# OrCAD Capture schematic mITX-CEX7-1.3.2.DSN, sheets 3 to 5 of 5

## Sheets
3 Connectors (2): size D; title: Micro BMC, NVME, USB serial, USB connectors
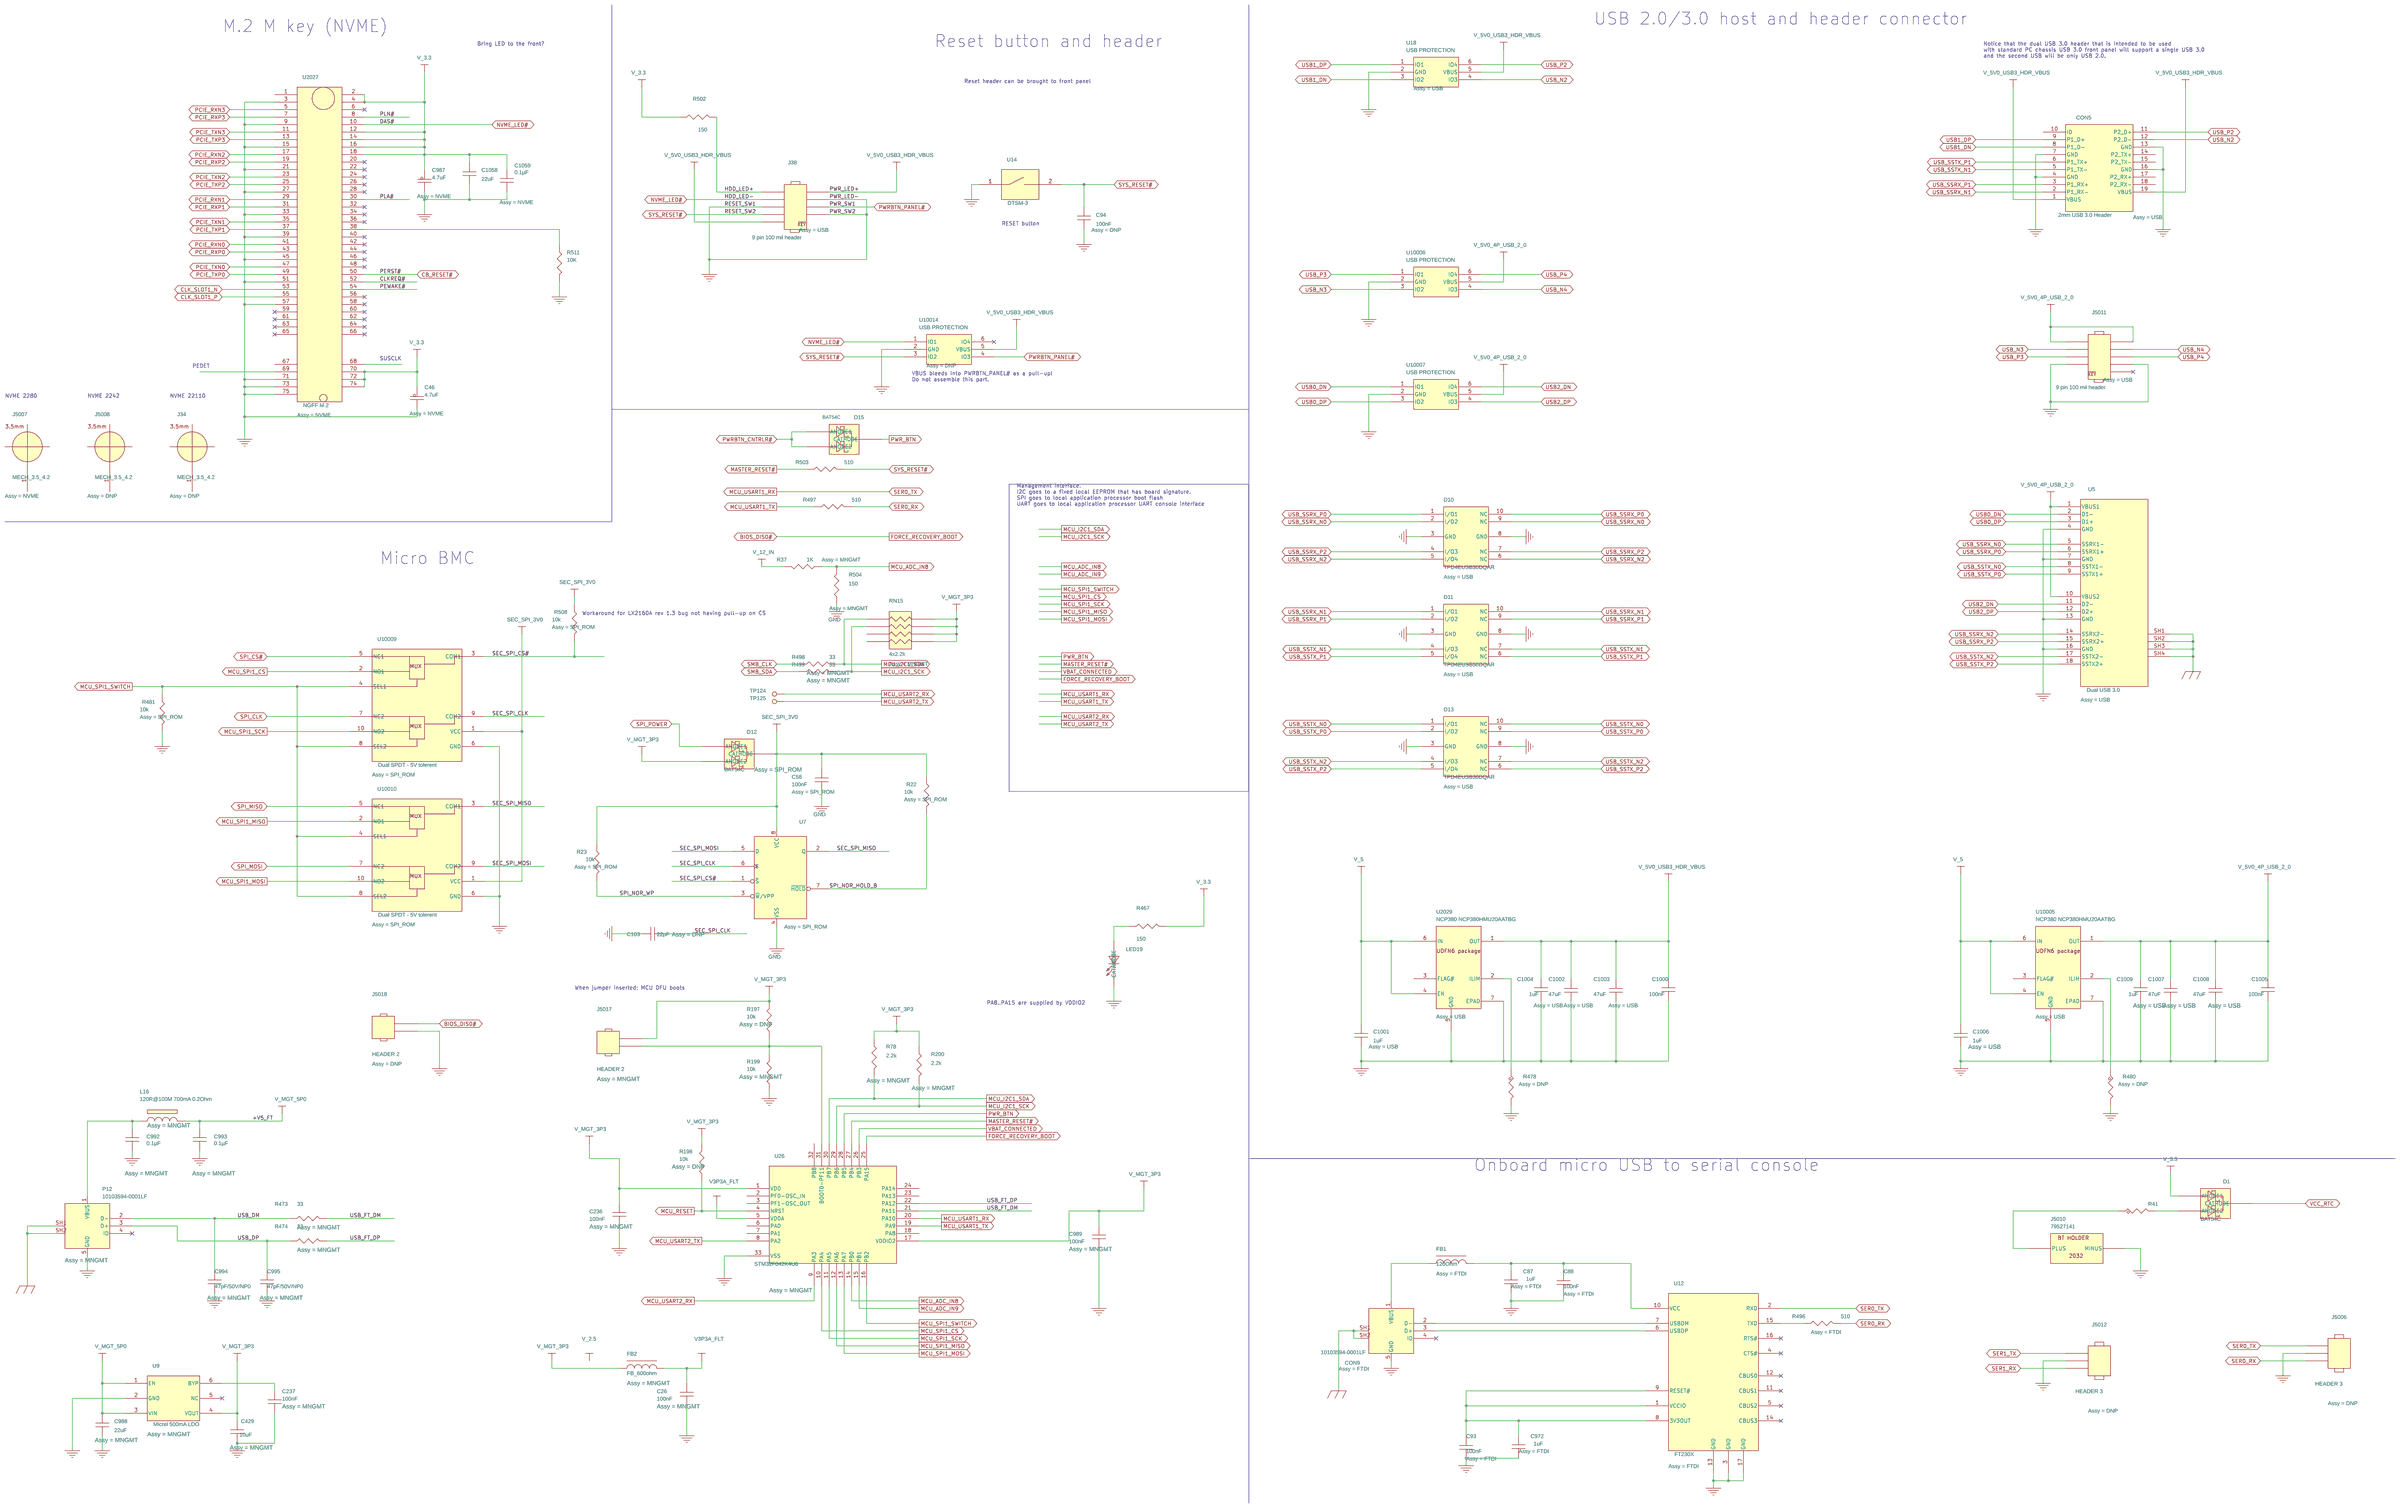
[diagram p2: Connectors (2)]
4 DC-DC: size D; title: ATX, 2x2 SFP+ connectors, power button controller
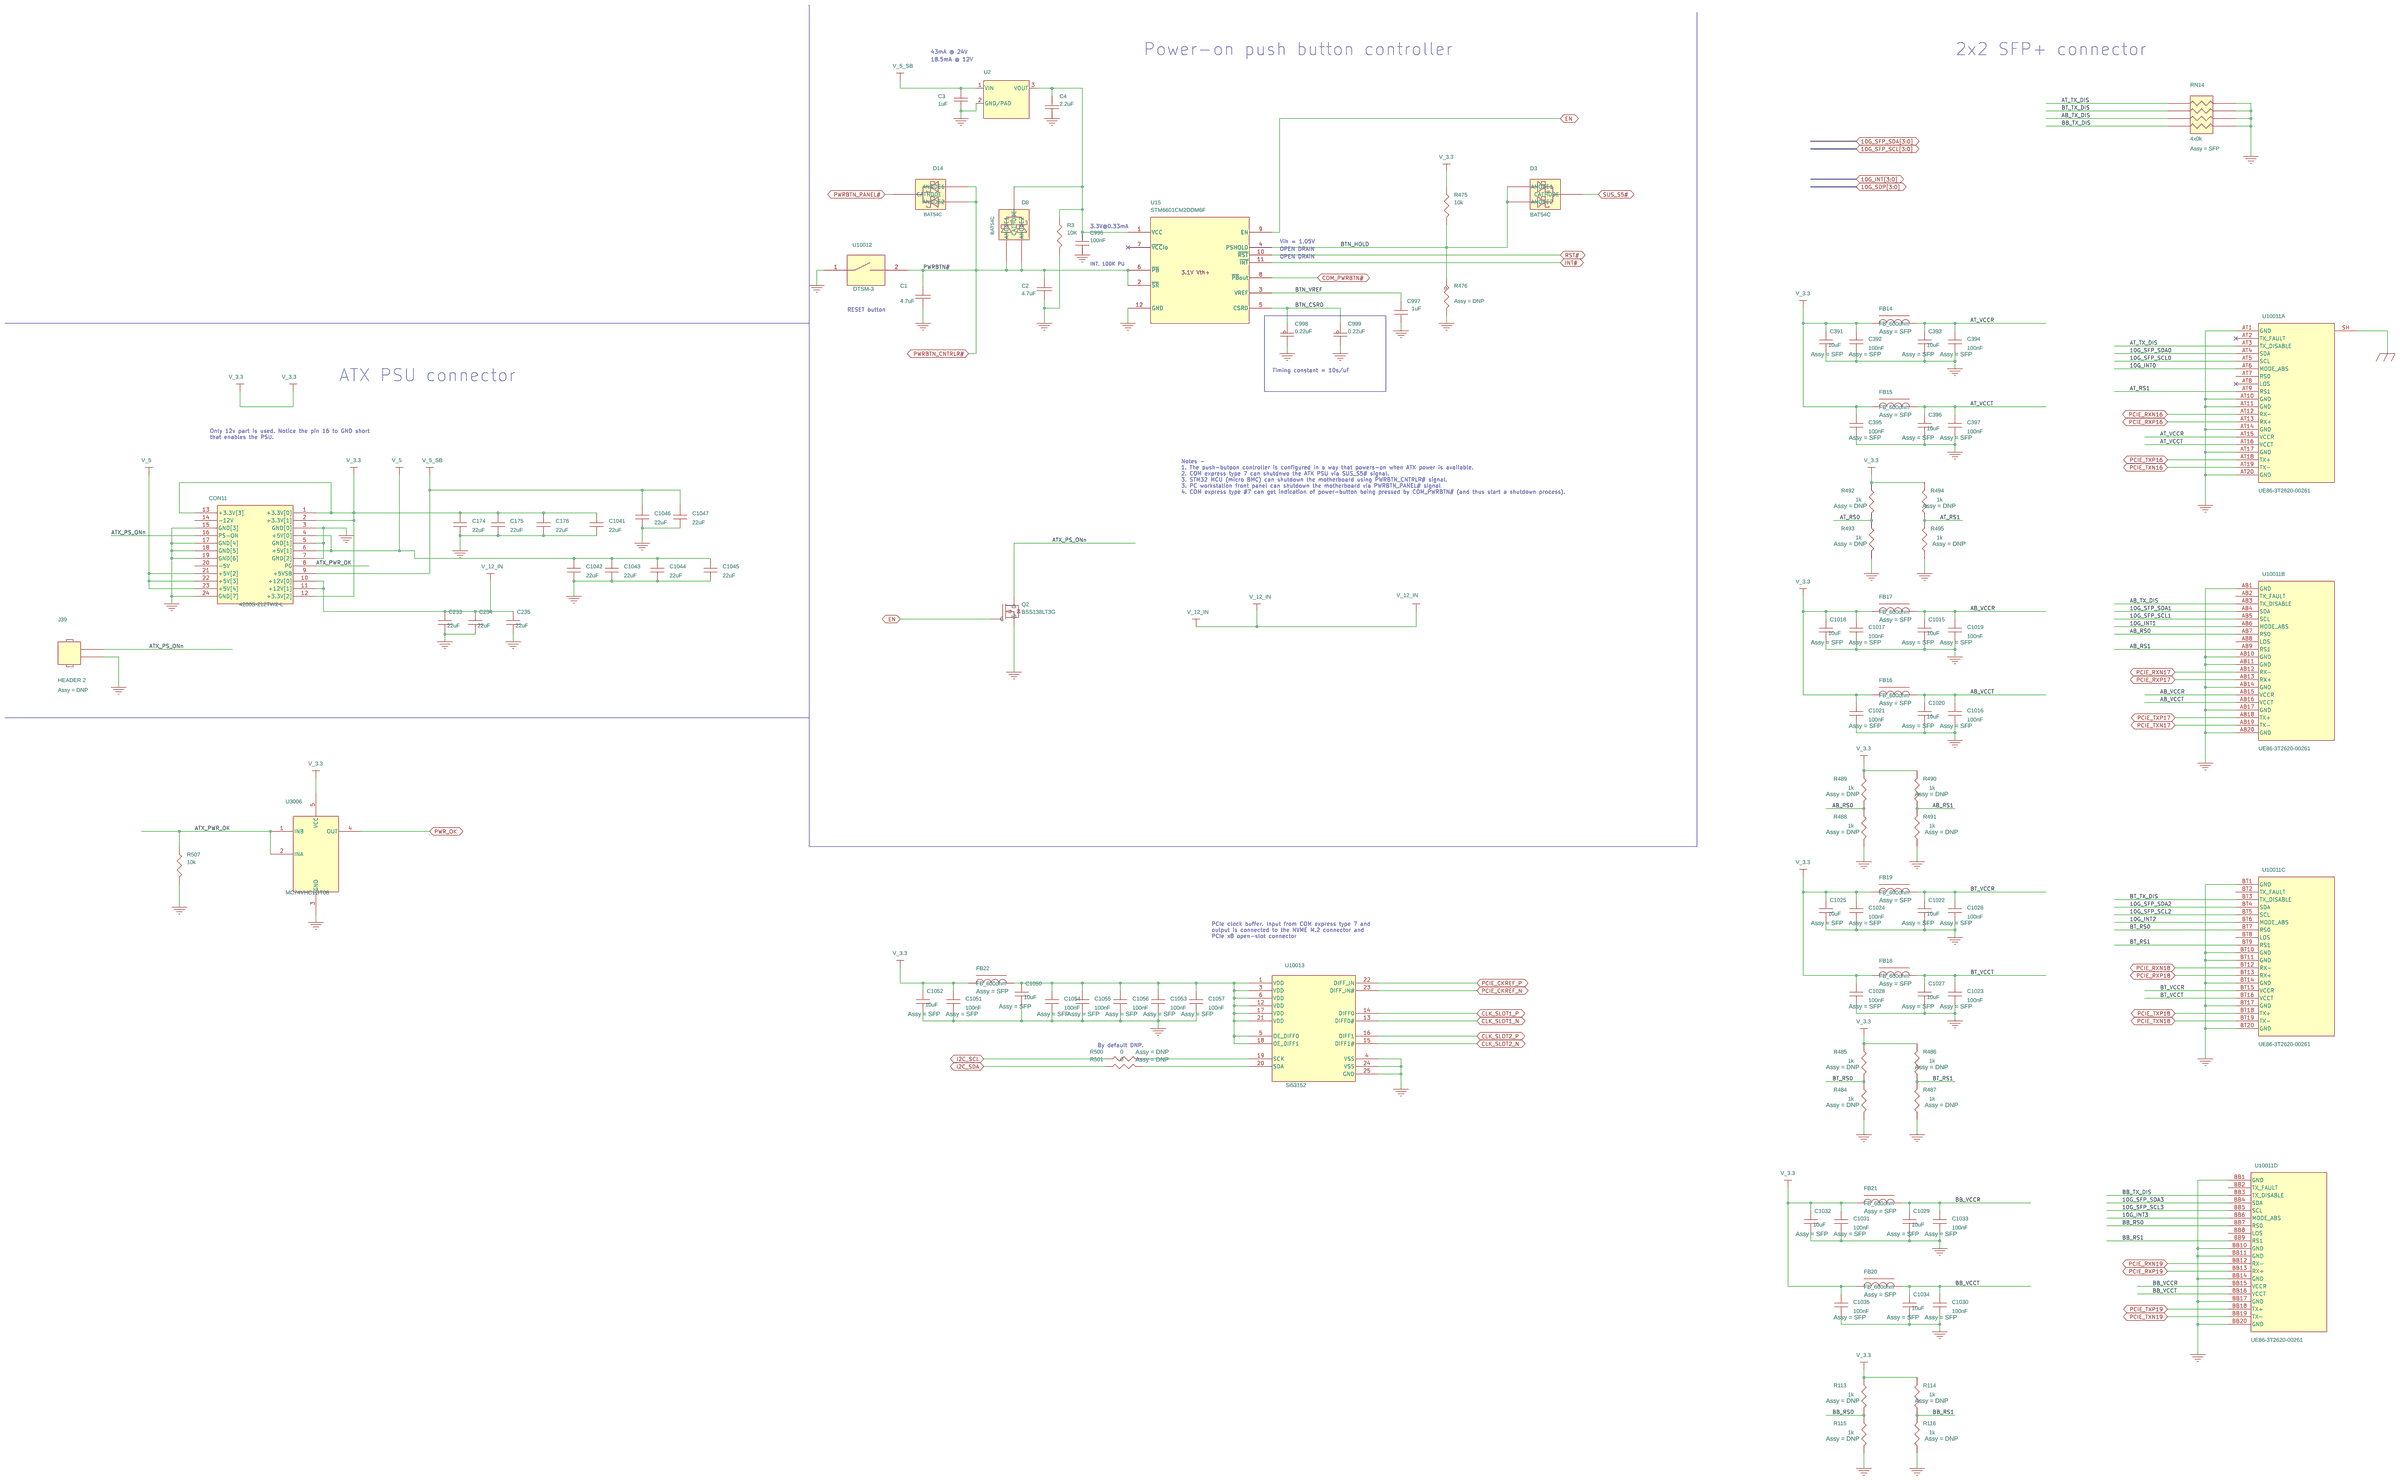
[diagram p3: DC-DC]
5 1588 PTP: size D; title: 1588 PTP - This circuit is not assembled by default
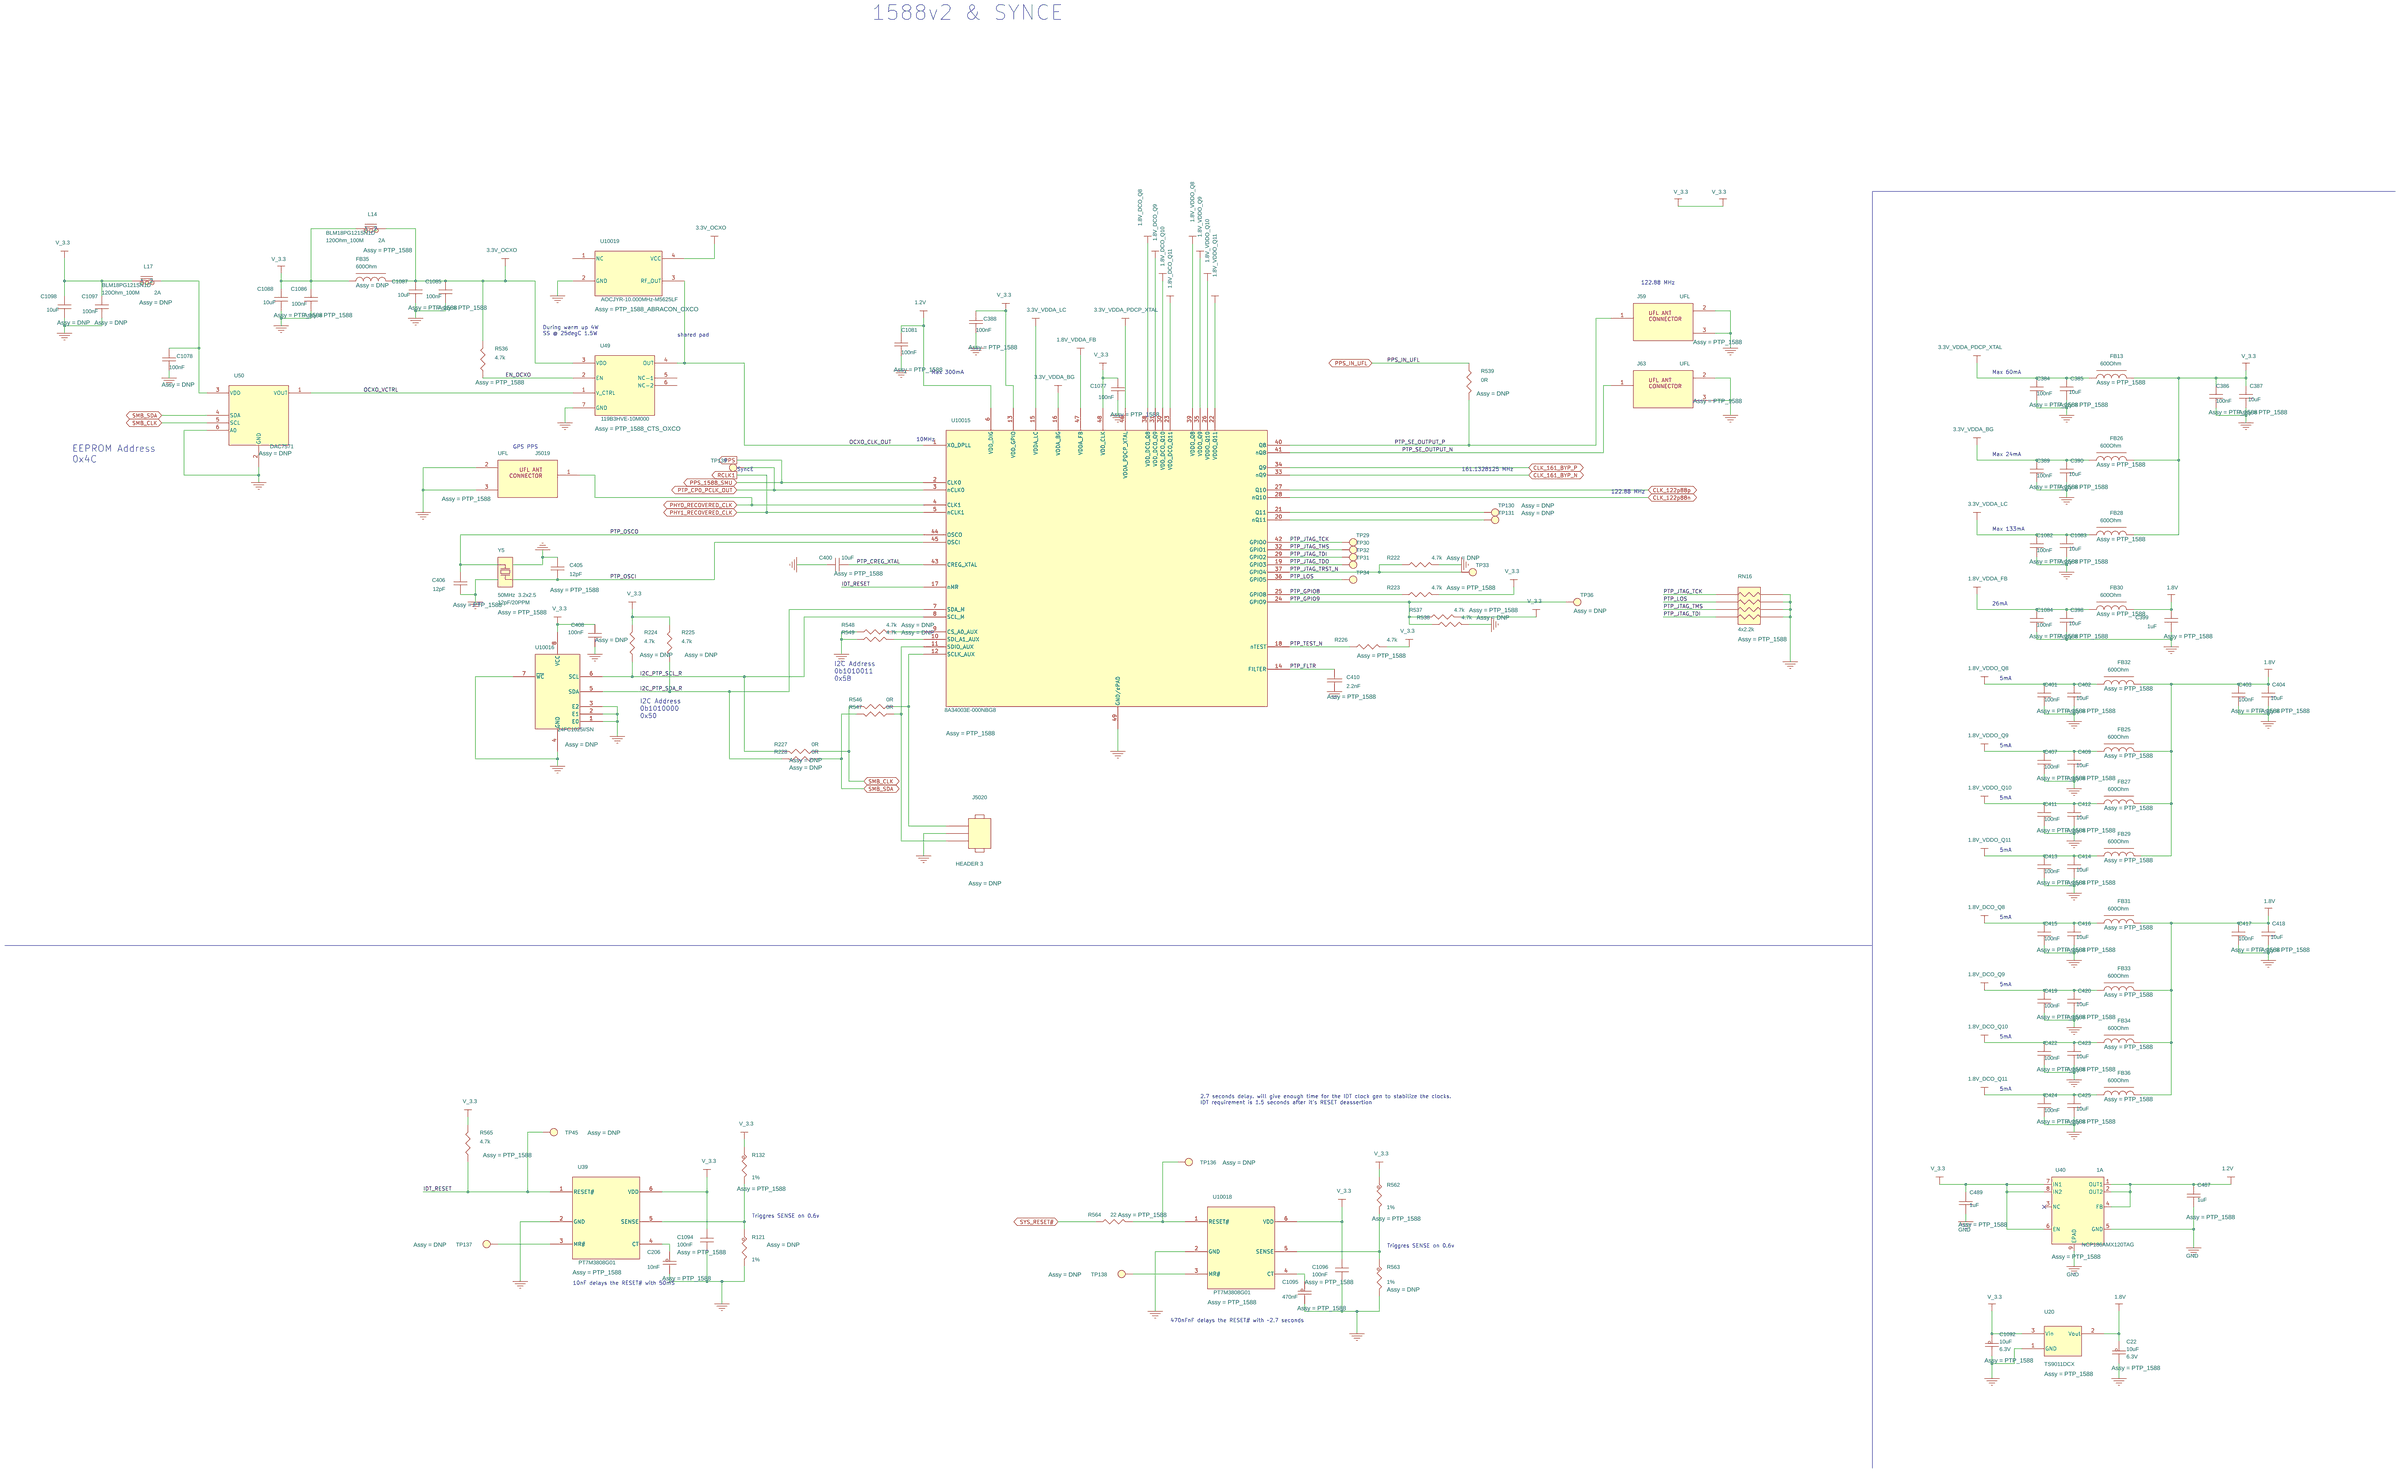
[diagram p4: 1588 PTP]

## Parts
sheet 1588 PTP
C22  10uF  [0603]
C206  10nF  [0402]
C384  100nF  [C0402]
C385  10uF  [C0603]
C386  100nF  [C0402]
C387  10uF  [C0603]
C388  100nF  [C0402]
C389  100nF  [C0402]
C390  10uF  [C0603]
C398  10uF  [C0603]
C399  1uF  [0402_SQR21]
C400  10uF  [C0603]
C401  100nF  [C0402]
C402  10uF  [C0603]
C403  100nF  [C0402]
C404  10uF  [C0603]
C405  12pF  [C0402]
C406  12pF  [C0402]
C407  100nF  [C0402]
C408  100nF  [C0402]
C409  10uF  [C0603]
C410  2.2nF  [C0402]
C411  100nF  [C0402]
C412  10uF  [C0603]
C413  100nF  [C0402]
C414  10uF  [C0603]
C415  100nF  [C0402]
C416  10uF  [C0603]
C417  100nF  [C0402]
C418  10uF  [C0603]
C419  100nF  [C0402]
C420  10uF  [C0603]
C422  100nF  [C0402]
C423  10uF  [C0603]
C424  100nF  [C0402]
C425  10uF  [C0603]
C487  1uF  [C0402]
C489  1uF  [C0402]
C1077  100nF  [C0402]
C1078  100nF  [C0402]
C1081  100nF  [C0402]
C1082  100nF  [C0402]
C1083  10uF  [C0603]
C1084  100nF  [C0402]
C1085  100nF  [C0402]
C1086  100nF  [C0402]
C1087  10uF  [C0603]
C1088  10uF  [C0603]
C1092  10uF  [0603]
C1094  100nF  [C0402]
C1095  470nF  [0402]
C1096  100nF  [C0402]
C1097  100nF  [C0402]
C1098  10uF  [C0603]
FB13  600Ohm  [L0603]
FB25  600Ohm  [L0603]
FB26  600Ohm  [L0603]
FB27  600Ohm  [L0603]
FB28  600Ohm  [L0603]
FB29  600Ohm  [L0603]
FB30  600Ohm  [L0603]
FB31  600Ohm  [L0603]
FB32  600Ohm  [L0603]
FB33  600Ohm  [L0603]
FB34  600Ohm  [L0603]
FB35  600Ohm  [L0603]
FB36  600Ohm  [L0603]
J59  UFL  [MHF]
J63  UFL  [MHF]
J5019  UFL  [MHF]
J5020  HEADER 3
L14  BLM18PG121SN1D  [BLM18PG121SN1D]
L17  BLM18PG121SN1D  [BLM18PG121SN1D]
R121  24.0K  [0402]
R132  12K  [R0402]
R222  4.7k  [R0402]
R223  4.7k  [R0402]
R224  4.7k  [R0402]
R225  4.7k  [R0402]
R226  4.7k  [R0402]
R227  0R  [R0402]
R228  0R  [R0402]
R536  4.7k  [R0402]
R537  4.7k  [R0402]
R538  4.7k  [R0402]
R539  0R  [R0402]
R546  0R  [R0402]
R547  0R  [R0402]
R548  4.7k  [R0402]
R549  4.7k  [R0402]
R562  12K  [R0402]
R563  24.0K  [0402]
R564  22  [R0402]
R565  4.7k  [R0402]
RN16  4x2.2k
TP29  R 35
TP30  R 35
TP31  R 35
TP32  R 35
TP33  R 35
TP34  R 35
TP36  R 35
TP45  Header_1x1  [HDR_1X1]
TP130  R 35
TP131  R 35
TP136  Header_1x1  [HDR_1X1]
TP137  Header_1x1  [HDR_1X1]
TP138  Header_1x1  [HDR_1X1]
TP139  R 35
U20  TS9011DCX  [SOT-23-3]
U39  PT7M3808G01
U40  NCP186AMX120TAG  [NCP186AMX120TAG]
U49  119B3HVE-10M000
U50  DAC7571
U10015  8A34003E-000NBG8
U10016  24FC1025I/SN  [SO8]
U10018  PT7M3808G01
U10019  AOCJYR-10.000MHz-M5625LF
Y5  50MHz  3.2x2.5  [FA-128]
sheet Connectors (2)
C26  100nF
C46  4.7uF
C58  100nF
C87  1uF
C88  100nF
C93  100nF
C94  100nF
C103  22pF
C236  100nF
C237  100nF
C429  10uF
C972  1uF
C987  4.7uF
C988  22uF
C989  100nF
C992  0.1µF  [RC0402]
C993  0.1µF  [RC0402]
C994  47pF/50V/NP0  [311-1021-1-ND]
C995  47pF/50V/NP0  [311-1021-1-ND]
C1000  100nF
C1001  1uF
C1002  47uF
C1003  47uF
C1004  1uF
C1005  100nF
C1006  1uF
C1007  47uF
C1008  47uF
C1009  1uF
C1058  22uF
C1059  0.1µF  [RC0402]
CON5  2mm USB 3.0 Header
CON9  10103594-0001LF
D1  BAT54C
D10  TPD4EUSB30DQAR  [296-28063-1-ND]
D11  TPD4EUSB30DQAR  [296-28063-1-ND]
D12  BAT54C
D13  TPD4EUSB30DQAR  [296-28063-1-ND]
D15  BAT54C
FB1  120Ohm
FB2  FB_600ohm
J34  MECH_3.5_4.2  [MECH_2.5_4]
J38  9 pin 100 mil header
J5006  HEADER 3
J5007  MECH_3.5_4.2  [MECH_2.5_4]
J5008  MECH_3.5_4.2  [MECH_2.5_4]
J5010  79527141  [BT00006]
J5011  9 pin 100 mil header
J5012  HEADER 3
J5017  HEADER 2
J5018  HEADER 2
L16  120R@100M 700mA 0.2Ohm  [240-2367-1-ND]
LED19  SMT Green
P12  10103594-0001LF
R22  10k
R23  10k
R37  1K
R41  1K
R78  2.2k
R197  10k
R198  10k
R199  10k
R200  2.2k
R467  150
R473  33  [RC0402]
R474  33  [RC0402]
R478  0
R480  0
R481  10k
R496  510
R497  510
R498  33  [RC0402]
R499  33  [RC0402]
R502  150
R503  510
R504  150
R508  10k
R511  10K  [0402]
RN15  4x2.2k
TP124  TESTPOINT  [TESTPOINT]
TP125  TESTPOINT  [TESTPOINT]
U5  Dual USB 3.0
U7  W25Q32BVZPIG
U9  Micrel 500mA LDO
U12  FT230X  [QFN16]
U14  DTSM-3  [DTSM-3]
U18  USB PROTECTION  [568-3529-1-ND]
U26  STM32F042K4U6  [UFQFPN32_5x5]
U2027  NGFF M.2  [NGFF]
U2029  NCP380 NCP380HMU20AATBG  [TSOP-5]
U10005  NCP380 NCP380HMU20AATBG  [TSOP-5]
U10006  USB PROTECTION  [568-3529-1-ND]
U10007  USB PROTECTION  [568-3529-1-ND]
U10009  Dual SPDT - 5V tolerent  [R-PUQFN-N10]
U10010  Dual SPDT - 5V tolerent  [R-PUQFN-N10]
U10014  USB PROTECTION  [568-3529-1-ND]
sheet DC-DC
C1  4.7uF  [C0805]
C2  4.7uF  [C0805]
C3  1uF
C4  2.2uF
C174  22uF
C175  22uF
C176  22uF
C233  22uF
C234  22uF
C235  22uF
C391  10uF
C392  100nF
C393  10uF
C394  100nF
C395  100nF
C396  10uF
C397  100nF
C996  100nF
C997  1uF
C998  0.22uF
C999  0.22uF
C1015  10uF
C1016  100nF
C1017  100nF
C1018  10uF
C1019  100nF
C1020  10uF
C1021  100nF
C1022  10uF
C1023  100nF
C1024  100nF
C1025  10uF
C1026  100nF
C1027  10uF
C1028  100nF
C1029  10uF
C1030  100nF
C1031  100nF
C1032  10uF
C1033  100nF
C1034  10uF
C1035  100nF
C1041  22uF
C1042  22uF
C1043  22uF
C1044  22uF
C1045  22uF
C1046  22uF
C1047  22uF
C1050  10uF
C1051  100nF
C1052  10uF
C1053  100nF
C1054  100nF
C1055  100nF
C1056  100nF
C1057  100nF
CON11  4200S-212TW2-L
D3  BAT54C
D8  BAT54C
D14  BAT54C
FB14  FB_600ohm
FB15  FB_600ohm
FB16  FB_600ohm
FB17  FB_600ohm
FB18  FB_600ohm
FB19  FB_600ohm
FB20  FB_600ohm
FB21  FB_600ohm
FB22  FB_600ohm
J39  HEADER 2
Q2  BSS138LT3G  [BSS138LT3GOSTR-ND]
R3  10K  [0402]
R113  1k
R114  1k
R115  1k
R116  1k
R475  10k
R476  30K
R484  1k
R485  1k
R486  1k
R487  1k
R488  1k
R489  1k
R490  1k
R491  1k
R492  1k
R493  1k
R494  1k
R495  1k
R500  0
R501  0
R507  10k
RN14  4x0k
U2  LDO 3.3V
U15  STM6601CM2DDM6F  [497-10132-1-ND]
U3006  MC74VHC1GT08  [SOT-353]
U10011  UE86-3T2620-00261  (sections A,B,C,D)
U10012  DTSM-3  [DTSM-3]
U10013  Si53152

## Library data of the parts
C22 C1092 = CAP_NP: CAP CER 10UF 6.3V 10% X5R 0603; AGILE_PN: 150-77832; Assy: PTP_1588; CAD_APPROVED: Yes; FPLIST: CC0603_OV,CC0603,0603_CC; HEIGHT: 1.0MM; MFG_NAME01: TDK; MFG_PN01: C1608X5R0J106KT; PRIORITY_PN: CA30001; ROHS: Yes; SIGNAL_MODEL: DEFAULT_CAPACITOR_1e+07pF_2_1; SolidRun P/N: CA30001; Tolerance: 10%; WVDC: 6.3V
C206 = CAP_NP: CAP CER 0.01UF 6.3V 10% X7R 0402; AGILE_PN: 150-75465; Assy: PTP_1588; CAD_APPROVED: YES; FPLIST: CC0201,CC0201_HD,0201_CC,cc_0201_cir; HEIGHT: 0.33 MM; MFG_NAME01: MURATA; MFG_PN01: GRM033R70J103KA01D; ROHS: Yes; ROOM: CPU; SIGNAL_MODEL: DEFAULT_CAPACITOR_10000pF_2_1; SolidRun P/N: CA20081; Tolerance: 10%; VOLTAGE: 6.3V; WVDC: 6.3V
C384 C386 C389 C401 C403 C407 C411 C413 C415 C417 C419 C422 C424 C1082 C1084-C1086 = Cap: CAP CER 0402 100nF 10V 10% X7R; Assy: PTP_1588; Manufacturer: samsung; Manufacturer P/N: CL05B104KP5NNNC; Part Number: C1040402-X7R-16V; Power: <null>; SolidRun P/N: CA20001; Tolerance: 6.3V 20% X7R; Datasheet: <null>
C385 C387 C390 C398 C402 C404 C409 C412 C414 C416 C418 C420 C423 C425 C1083 C1087 C1088 = Cap: CAP CER 0603 10UF 6.3V 10% X5R; Assy: PTP_1588; Manufacturer: Samsung; Manufacturer P/N: CL10A106KQ8NNNC; Part Number: C1060805-X5R-16V; Power: <null>; SolidRun P/N: CA30001; Tolerance: 20%; Datasheet: <null>
C388 C1077 C1081 = CAP_NP1: CAP CER 0.1uF ±10% 16V X7R 0402; Assy: PTP_1588; Category : Capacitors (Size: 0402); Digikey P/N: 1276-1001-1-ND; Manufacturer: Samsung Electro-Mechanics; Part Num#: CL05B104KO5NNNC; Rating: 16V; SolidRun P/N: CA20013
C399 = Cap: CAP CER 0402 1uF 10V 10% X5R; Assy: PTP_1588; FPLIST: 0402_SQR21,0402_RND,0402,0402_OCT; Manufacturer: Samsung; Manufacturer P/N: CL05A105KP5NNNC; Part Number: GMC04X5R105K25NT; SolidRun P/N: CA20005; Tolerance: 10%
C400 = Cap: CAP CER 10UF 6.3V 10% X5R 0603; Assy: PTP_1588; Manufacturer: SAMSUNG; Manufacturer P/N: CL10A106KQ8NNNC; Part Number: C1060805-X5R-16V; SolidRun P/N: CA30001; Updated: 2015-02-17 20:35:06; Datasheet: <null>
C405 C406 = CAP_NP1: CAP CER 12pF 50V 10% COG 0402; Assy: PTP_1588; Category : Capacitors (Size: 0402); Digikey P/N: 311-1643-1-ND; Manufacturer: YAGEO; Part Num#: GRM1555C1H120JZ01D; Rating: 50V; SolidRun P/N: CA20149
C408 = Cap: CHIP CAP 0.1uF 6.3V 0402 X5R; Assy: DNP; FPLIST: 0402_SQR21,0402_RND,0402; Manufacturer: SAMSUNG; Manufacturer Name: samsung; Manufacturer P/N: CL05B104KP5NNNC; Part Number: C1040402-X7R-16V; SolidRun P/N: CA20001; Updated: 2016-02-10 17:13:33; Datasheet: <null>
C410 = CAP-2.2nF-25V-0603: Assy: PTP_1588; Manufacturer: Murata; Manufacturer P/N: GRM188R71E222KA01D; SolidRun P/N: CA30025
C487 C489 = CAP_NP1: CAP CER 1UF 10V X5R 0402; Assy: PTP_1588; Category : Capacitors (Size: 0402); Digikey P/N: 1276-1076-1-ND; Manufacturer: Samsung Electro-Mechanics; Part Num#: CL05A105KP5NNNC; Rating: 10V; SolidRun P/N: CA20005
C1078 = CAP_NP1: CAP CER 0.1uF ±10% 16V X7R 0402; Assy: DNP; Category : Capacitors (Size: 0402); Digikey P/N: 1276-1001-1-ND; Manufacturer: Samsung Electro-Mechanics; Part Num#: CL05B104KO5NNNC; Rating: 16V; SolidRun P/N: CA20013
C1094 C1096 = Cap: CAP CER 0402 100nF 10V 10% X7R; Assy: PTP_1588; FPLIST: 0402_SQR21,0402_RND,0402; Manufacturer: samsung; Manufacturer Name: samsung; Manufacturer P/N: CL05B104KP5NNNC; Part Number: C1040402-X7R-16V; SolidRun P/N: CA20001; Updated: 2016-02-10 17:13:33; Datasheet: <null>
C1095 = CAP_NP: CAP CER 470nF 6.3V 10% X5R 0402; AGILE_PN: 150-75465; Assy: PTP_1588; CAD_APPROVED: YES; FPLIST: CC0201,CC0201_HD,0201_CC,cc_0201_cir; HEIGHT: 0.33 MM; ROHS: Yes; ROOM: CPU; SIGNAL_MODEL: DEFAULT_CAPACITOR_10000pF_2_1; SolidRun P/N: CA20801; Tolerance: 10%; VOLTAGE: 6.3V; WVDC: 6.3V
C1097 = Cap: CAP CER 0402 100nF 10V 10% X7R; Assy: DNP; Manufacturer: samsung; Manufacturer P/N: CL05B104KP5NNNC; Part Number: C1040402-X7R-16V; Power: <null>; SolidRun P/N: CA20001; Tolerance: 6.3V 20% X7R; Datasheet: <null>
C1098 = Cap: CAP CER 0603 10UF 6.3V 10% X5R; Assy: DNP; Manufacturer: Samsung; Manufacturer P/N: CL10A106KQ8NNNC; Part Number: C1060805-X5R-16V; Power: <null>; SolidRun P/N: CA30001; Tolerance: 20%; Datasheet: <null>
FB13 FB25-FB34 FB36 = Ferrite_Bead_v3: Multilayer Ferrite Chip Beads 600 OHM; Assy: PTP_1588; Manufacturer: chilisin; Manufacturer P/N: PBY160808T-601Y-N; Part Number: PBY160808T-601Y-N; SolidRun P/N: IN00012; Updated: 2015-02-17 20:35:06; Datasheet: http://www.chilisin.com.tw/proimages/product_line_up_pdf/Chip%20Beads%20PB%20Series.pdf
FB35 = Ferrite_Bead_v3: Multilayer Ferrite Chip Beads 600 OHM; Assy: DNP; Manufacturer: chilisin; Manufacturer P/N: PBY160808T-601Y-N; Part Number: PBY160808T-601Y-N; SolidRun P/N: IN00012; Updated: 2015-02-17 20:35:06; Datasheet: http://www.chilisin.com.tw/proimages/product_line_up_pdf/Chip%20Beads%20PB%20Series.pdf
J59 J63 J5019 = UFL: Assy: PTP_1588; MFG_NAME01: i-pex; MFG_PN01: 20314-001 E- 01; Manufacturer: Hirose; Manufacturer Name: Hirose; Manufacturer P/N: ufl-r-smt(10); SolidRun P/N: CO00095; Datasheet: http://www.i-pex.com/products/Catalog_E/C_MHF_E.pdf
J5006 J5012 J5020 = HEADER_3: Assy: DNP; SolidRun P/N: CO00509
L14 = Ferrite_Bead: Bead 120ohm, 100MHz, 2A; Assy: PTP_1588; Category : COILS-FERRIT; Digikey P/N: 490-1037-2-ND; Manufacturer: Murata Electronics North America; Rating: 2A; SolidRun P/N: IN00003; Vol: 120Ohm_100M; Datasheet: https://www.murata.com/en-us/products/productdata/8796738650142/ENFA0003.pdf
L17 = Ferrite_Bead: Bead 120ohm, 100MHz, 2A; Assy: DNP; Category : COILS-FERRIT; Digikey P/N: 490-1037-2-ND; Manufacturer: Murata Electronics North America; Rating: 2A; SolidRun P/N: IN00003; Vol: 120Ohm_100M; Datasheet: https://www.murata.com/en-us/products/productdata/8796738650142/ENFA0003.pdf
R121 R563 = RES: RES MF 24.0K 1/16W 1% 0402; AGILE_PN: 470-75416; Assy: DNP; CAD_APPROVED: Yes; FPLIST: RC0402_25,RC0402_HD,0402_CC; MFG_NAME01: VISHAY INTERTECHNOLOGY; MFG_PN01: CRCW040224K0FKED; ROHS: Yes; SIGNAL_MODEL: DEFAULT_RESISTOR_24000OHM_2_1; SolidRun P/N: RE20038; Tolerance: 1%
R132 R562 = RES: RES MF 12.0K 1/16W 1% 0402; AGILE_PN: 470-75416; Assy: PTP_1588; CAD_APPROVED: Yes; FPLIST: RC0402_25,RC0402_HD,0402_CC; ROHS: Yes; SIGNAL_MODEL: DEFAULT_RESISTOR_21000OHM_2_1; SolidRun P/N: RE20462; Tolerance: 1%
R222 R224 R225 R538 R548 R549 = R-1K-0402: RES 4.7K OHM 1/16W 1% 0402 SMD; Assy: DNP; Manufacturer P/N: RC0402FR-074K7L; Rated Voltage: 1/16W; SolidRun P/N: RE20497
R223 R226 R536 R537 R565 = R-1K-0402: RES 4.7K OHM 1/16W 1% 0402 SMD; Assy: PTP_1588; Manufacturer P/N: RC0402FR-074K7L; Rated Voltage: 1/16W; SolidRun P/N: RE20497
R227 R228 R539 = Resistor: RES MF ZERO OHM 1/10W -- 0446; Assy: DNP; Manufacturer: YAGEO; Manufacturer P/N: RC0402JR-070RL; Part Number: R0000402; Rated Voltage: 1/10W; SolidRun P/N: RE20009; Updated: 17/02/2015 20:35
R546 R547 = Resistor: RES MF ZERO OHM 1/10W -- 0446; Manufacturer: YAGEO; Manufacturer P/N: RC0402JR-070RL; Part Number: R0000402; Rated Voltage: 1/10W; SolidRun P/N: RE20009; Updated: 17/02/2015 20:35
R564 = Resistor: RES 0402 1/16W 22? 5%; Assy: PTP_1588; Manufacturer: Yageo; Manufacturer P/N: RC0402JR-0722RL; Part Number: R2200402-1%; Power: <null>; SolidRun P/N: RE20021; Tolerance: 5%; Datasheet: <null>
RN16 = RESISTOR_DIP_4: 4 Elements 2.2kOhms 5 %; Assy: PTP_1588; SolidRun P/N: RN00045
TP29-TP34 TP36 TP130 TP131 TP139 = T_POINT_R: TEST POINT MINIATURE SMT; AGILE_PN: 510-75618; Assy: DNP; CAD_APPROVED: Yes; Category : Test Point; HEIGHT: 0.1MM; ROHS: Yes
TP45 TP136-TP138 = T_POINT_R: TEST POINT MINIATURE SMT; Assembly Footprint: 100Mil_T/H; Assy: DNP; Manufacturer: PCB; Manufacturer P/N: N/A; Part Number: BPEG40SS-GBR_1x1, TSW-150-23-G-S; SolidRun P/N: TP00001; Datasheet: <null>
U20 = MC70L15_TO3_0: LDO - 1.8V output, 0.25A, 12V maximum inout; Assy: PTP_1588; MFG_NAME01: Taiwan Semiconductors; PRIORITY_PN: IC00014; SolidRun P/N: IC00014; Datasheet: http://www.ts.com.tw/DSfile/TS9011_E07.pdf
U39 U10018 = PT7M3808G01: Assy: PTP_1588; SolidRun P/N: IC01327
U40 = IC-NCP186AMX120TAG: Linear Voltage Regulator IC Positive Fixed Output 1.2V 1A 8-XDFN (1.6x1.2); Assy: PTP_1588; Category : IC-PWR-LDO; Digikey P/N: NCP186AMX120TAGOSTR-ND; Manufacturer: ON Semiconductor; Rating: 1A; SolidRun P/N: IC01120; VOL: 1.2V; Datasheet: http://www.onsemi.com/pub/Collateral/NCP186-D.PDF
U49 = OC00041_0: Assy: PTP_1588_CTS_OXCO; SolidRun P/N: OC00041
U50 = IC01522: Assy: DNP
U10015 = IC01516: Assy: PTP_1588
U10016 = M24C0x-FDW: EEPROM Memory IC 1Mb (256 x 8) I²C 400kHz 900ns SO8; Assy: DNP; Manufacturer: STMicroelectronics; Manufacturer Name: STMicroelectronics; Manufacturer P/N: M24C02-MWN6TP; PRIORITY_PN: IC01168; SolidRun P/N: IC01521
U10019 = AOCJYR-10.000MHz-M5625LF: Assy: PTP_1588_ABRACON_OXCO; SolidRun P/N: OC00042
Y5 = XTAL-4P: XTAL 50MHZ Load-Capacitive=12pF -- 3.2X2.5MM SMT; Assy: PTP_1588; Category : OC-CRYSTAL; Digikey P/N: SER4186TR-ND; Manufacturer: Raltron; Rating: 12pF/20PPM; SolidRun P/N: OC00019; Datasheet: https://support.epson.biz/td/api/doc_check.php?dl=brief_FA-128_en.pdf
C26 C236 C237 C989 = Cap: CAP CER 0402 100nF 10V 10% X7R; Assy: MNGMT; SolidRun P/N: CA20001
C46 C987 = CAP_NP: CAP CER 4.7 6.3V 10% X5R 0402; Assy: NVME; SolidRun P/N: CA20800
C58 = Cap: Assy: SPI_ROM; SolidRun P/N: CA20001
C87 C972 = Cap: Assy: FTDI; SolidRun P/N: CA20005
C88 C93 = Cap: Assy: FTDI; SolidRun P/N: CA20001
C94 = Cap: Assy: DNP; SolidRun P/N: CA20001
C103 = Cap: CAP CER 0402 22pF 50V 5% C0G; Assy: DNP; SolidRun P/N: CA20080
C429 = Cap: Assy: MNGMT; SolidRun P/N: CA30001
C988 = Cap: CAP CER 0603 22UF 6.3V 20% X5R; Assy: MNGMT; SolidRun P/N: CA30002
C992 C993 = CAP_CER_0.1UF_16V_10%_X7R_0402: Assy: MNGMT; SolidRun P/N: CA20013
C994 C995 = CAP_CER_47PF_50V_5%_NPO_0402: Assy: MNGMT; SolidRun P/N: CA20144
C1000 C1005 = Cap: SolidRun P/N: CA20001
C1001 C1004 C1006 C1009 = Cap: Assy: USB; SolidRun P/N: CA20005
C1002 C1003 C1007 C1008 = Cap: Assy: USB; SolidRun P/N: CA50001
C174-C176 C1041-C1047 C1058 = Cap: CAP CER 0603 22UF 6.3V 20% X5R; SolidRun P/N: CA30002
C1059 = CAP_CER_0.1UF_16V_10%_X7R_0402: Assy: NVME; SolidRun P/N: CA20013
CON5 = BH1S-20G_JTAG_3: Assy: USB; SolidRun P/N: CO00758
CON9 = CU04SCH15B0_1: Assy: FTDI; SolidRun P/N: CO00005
D1 D3 D8 D14 D15 = BAT54C: SolidRun P/N: DI00001
D10 D11 D13 = TVS_ESD_USB3.0_4CH_10SON: Assy: USB; SolidRun P/N: DI00247
D12 = BAT54C: Assy: SPI_ROM; SolidRun P/N: DI00001
FB1 = Ferrite_Bead_v3: Assy: FTDI; SolidRun P/N: IN00003
FB2 = Ferrite_Bead_v3: Multilayer Ferrite Chip Beads 0402 600ohm 500mA +/-25%; Assy: MNGMT; SolidRun P/N: IN00013
J34 J5008 = MECH_4.5_4: Assy: DNP; SolidRun P/N: MCH0008
J38 = HEADER_4x2_SM_5: Assy: USB; SolidRun P/N: CO00733
J5007 = MECH_4.5_4: Assy: NVME; SolidRun P/N: MCH0008
J5010 = CONN_BATT_HOLDER_2032_79527141
J5011 = HEADER_4x2_SM_4: Assy: USB; SolidRun P/N: CO00759
J5017 = HEADER_2: Assy: MNGMT; SolidRun P/N: CO00049
J39 J5018 = HEADER_2: Assy: DNP; SolidRun P/N: CO00049
L16 = FERRITE_700MA_120_OHM_0603_SMD: Assy: MNGMT; SolidRun P/N: IN00104
LED19 = LED: SolidRun P/N: DI00008
P12 = CU04SCH15B0_1: microUSB Type B connector; Assy: MNGMT; SolidRun P/N: CO00005
R22 R23 R481 R508 = Resistor: Assy: SPI_ROM; SolidRun P/N: RE20013
R37 = Resistor: RES 0402 1/16W 1K 5%; Assy: MNGMT; SolidRun P/N: RE20010
R41 = RES: SolidRun P/N: RE20010
R78 R200 = Resistor: CHIP RES 2.2K 1/16W 0402; Assy: MNGMT; SolidRun P/N: RE20204
R197 R198 = Resistor: RES 0402 1/16W 10K? 1%; Assy: DNP; SolidRun P/N: RE20013
R199 = Resistor: RES 0402 1/16W 10K? 1%; Assy: MNGMT; SolidRun P/N: RE20013
R467 R502 = Resistor: SolidRun P/N: RE20014
R473 R474 R498 R499 = RES_33.0_OHM_1_16W_1%_0402_SMD: Assy: MNGMT; SolidRun P/N: RE20502
R478 R480 = RES: Assy: DNP; SolidRun P/N: RE20009
R496 = RES1: RES SMD 510 OHM 5% 1/16W 0402; Assy: FTDI; SolidRun P/N: RE20022
R497 R503 = RES1: RES SMD 510 OHM 5% 1/16W 0402; Assy: MNGMT; SolidRun P/N: RE20022
R504 = Resistor: Assy: MNGMT; SolidRun P/N: RE20014
R3 R511 = R-10K-0402
RN15 = RESISTOR_DIP_4: 4 Elements 2.2kOhms 5 %; Assy: MNGMT; SolidRun P/N: RN00045
TP124 TP125 = TESTPOINT: Assy: DNP; SolidRun P/N: TP00001
U5 = Dual_USB_3_0.0: Assy: USB; SolidRun P/N: CO00554
U7 = M25P32: Assy: SPI_ROM; SolidRun P/N: IC00311
U9 = Micrel_500mA_LDO: Low Dropout LDO, 3.3V/500mA; Assy: MNGMT; SolidRun P/N: IC00123
U12 = FT230X_4: Assy: FTDI; SolidRun P/N: IC00015
U14 U10012 = DTSM-3: SolidRun P/N: CO00098
U18 U10006 U10007 = IC_USB_DUAL_ESD_PROTECT_6TSOP: Assy: USB; SolidRun P/N: IC01197
U26 = STM32F042K4U6_1: Assy: MNGMT; SolidRun P/N: IC01015
U2027 = NGFF_M.2: Assy: NVME; SolidRun P/N: CO00514
U2029 U10005 = NCP380_2: Assy: USB; SolidRun P/N: IC01034
U10009 U10010 = Dual_SPDT: Dual analog switch; Assy: SPI_ROM; SolidRun P/N: IC01039
U10014 = IC_USB_DUAL_ESD_PROTECT_6TSOP: Assy: DNP; SolidRun P/N: IC01197
C1 C2 = CAP-47uF-6.3V-0805: CAP CER 4.7UF 6.3V 10% X5R 0603; SolidRun P/N: CA30003
C3 = CAP-1uF-35V-0402
C4 = CAP-2.2uF-6.3V-0402
C233-C235 = Cap: SolidRun P/N: CA60006
C391 C393 C396 C1015 C1018 C1020 C1022 C1025 C1027 C1029 C1032 C1034 C1050 C1052 = Cap: CAP CER 0603 10UF 6.3V 10% X5R; Assy: SFP; SolidRun P/N: CA30001
C392 C394 C395 C397 C1016 C1017 C1019 C1021 C1023 C1024 C1026 C1028 C1030 C1031 C1033 C1035 C1051 C1053-C1057 = Cap: CAP CER 0402 100nF 10V 10% X7R; Assy: SFP; SolidRun P/N: CA20001
C996 = Cap: CHIP CAP 0.1uF 6.3V 0402 X5R; SolidRun P/N: CA20001
C997 = Cap: CAP CER 0402 1uF 25V 20% X5R; SolidRun P/N: CA20132
C998 C999 = CAP_NP: 0.22uF ±10% 100V Ceramic Capacitor X7R 0805; SolidRun P/N: CA40009
CON11 = 5566_ATX: SolidRun P/N: CO00590
FB14-FB22 = Ferrite_Bead_v3: Multilayer Ferrite Chip Beads 0603 600ohm 1.3A +/-25%; Assy: SFP; SolidRun P/N: IN00068
Q2 = MOSFET_N-CH_50V_200MA_SOT-23: SolidRun P/N: TR00007
R113-R116 R484-R495 = Resistor: RES 0402 1/16W 1k 5%; Assy: DNP; SolidRun P/N: RE20010
R475 R507 = Resistor: RES 0402 1/16W 10K? 1%; SolidRun P/N: RE20013
R476 = RES: Assy: DNP; SolidRun P/N: RE20458
R500 R501 = Resistor: RES 0402 1/16W 0? 5%; Assy: DNP; SolidRun P/N: RE20009
RN14 = RESISTOR_DIP_4: 4 Elements zero ohms; Assy: SFP; SolidRun P/N: RN00039
U2 = U-LDO-3.3V-AP2204R
U15 = IC_PWR_BTN_CTL_ACTHI_3.1V_5.6S: IC SUPERVISOR 3.1V 12TDFN BUTON CONTROLLER ON/OFF CTRL; SolidRun P/N: IC01227
U3006 = MC74VHC1GT08: SolidRun P/N: IC00024
U10011 = UE86-3T2620-00261: Assy: SFP; SolidRun P/N: CO00735
U10013 = Si53152: 1:2 PCIe clock buffer gen 4; SolidRun P/N: IC01396

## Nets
1.2V: C487.1 C1081.1 U40.1(OUT1) U40.2(OUT2) U40.4(FB) U10015.6(VDD_DIG)
1.8V: C22.1 C399.1 C403.1 C404.1 C417.1 C418.1 FB25.1 FB27.1 FB29.1 FB30.1 FB31.1 FB32.1 FB33.1 FB34.1 FB36.1 U20.2(Vout)
1.8V_DCO_Q8: C415.1 C416.1 FB31.2 U10015.38(VDD_DCO_Q8)
1.8V_DCO_Q9: C419.1 C420.1 FB33.2 U10015.31(VDD_DCO_Q9)
1.8V_DCO_Q10: C422.1 C423.1 FB34.2 U10015.30(VDD_DCO_Q10)
1.8V_DCO_Q11: C424.1 C425.1 FB36.2 U10015.23(VDD_DCO_Q11)
1.8V_VDDA_FB: C398.1 C1084.1 FB30.2 U10015.47(VDDA_FB)
1.8V_VDDO_Q8: C401.1 C402.1 FB32.2 U10015.39(VDDO_Q8)
1.8V_VDDO_Q9: C407.1 C409.1 FB25.2 U10015.35(VDDO_Q9)
1.8V_VDDO_Q10: C411.1 C412.1 FB27.2 U10015.26(VDDO_Q10)
1.8V_VDDO_Q11: C413.1 C414.1 FB29.2 U10015.22(VDDO_Q11)
3.3V: C46.1 C174.2 C175.2 C176.2 C386.1 C387.1 C388.1 C391.1 C392.1 C395.1 C408.1 C489.1 C987.1 C1017.1 C1018.1 C1021.1 C1024.1 C1025.1 C1028.1 C1031.1 C1032.1 C1035.1 C1041.2 C1051.1 C1052.1 C1058.2 C1059.1 C1077.1 C1086.1 C1088.1 C1092.1 C1094.1 C1096.1 C1097.1 C1098.1 CON11.1(+3.3V[0]) CON11.2(+3.3V[1]) CON11.12(+3.3V[2]) CON11.13(+3.3V[3]) D1.1(ANODE1) FB13.1 FB14.1 FB15.1 FB16.1 FB17.1 FB18.1 FB19.1 FB20.1 FB21.1 FB22.1 FB26.1 FB28.1 FB35.1 L14.1 L17.1 R113.2 R114.2 R132.1 R223.2 R224.2 R225.2 R226.2 R467.1 R475.2 R485.2 R486.2 R489.2 R490.2 R492.2 R494.2 R502.1 R537.2 R562.1 R565.2 U20.3(Vin) U39.6(VDD) U40.6(EN) U40.7(IN1) U40.8(IN2) U2027.2 U2027.4 U2027.12 U2027.14 U2027.16 U2027.18 U2027.70 U2027.72 U2027.74 U3006.5(VCC) U10015.13(VDD_GPIO) U10015.48(VDD_CLK) U10016.8(VCC) U10018.6(VDD) ; also on sheet 2
3.3V_OCXO: C1085.1 C1087.1 FB35.2 L14.2 R536.2 U49.3(VDD) U10019.4(VCC)
3.3V_VDDA_BG: C389.1 C390.1 FB26.2 U10015.16(VDDA_BG)
3.3V_VDDA_LC: C1082.1 C1083.1 FB28.2 U10015.15(VDDA_LC)
3.3V_VDDA_PDCP_XTAL: C384.1 C385.1 FB13.2 U10015.46(VDDA_PDCP_XTAL)
+V12_COMX: C233.1 C234.1 C235.1 CON11.10(+12V[0]) CON11.11(+12V[1]) R37.2 ; also on sheet 1 2
GND: C1.2 C2.2 C3.2 C4.2 C22.2 C26.2 C46.2 C58.2 C87.2 C88.1 C93.1 C94.2 C103.1 C174.1 C175.1 C176.1 C206.2 C233.2 C234.2 C235.2 C236.2 C237.2 C384.2 C385.2 C386.2 C387.2 C388.2 C389.2 C390.2 C391.2 C392.2 C393.2 C394.2 C395.2 C396.2 C397.2 C398.2 C399.2 C400.1 C401.2 C402.2 C403.2 C404.2 C405.1 C406.2 C407.2 C408.2 C409.2 C410.1 C411.2 C412.2 C413.2 C414.2 C415.2 C416.2 C417.2 C418.2 C419.2 C420.2 C422.2 C423.2 C424.2 C425.2 C429.2 C487.2 C489.2 C972.2 C987.2 C988.1 C989.2 C992.2 C993.2 C994.2 C995.2 C996.2 C997.1 C998.2 C999.2 C1000.2 C1001.1 C1002.1 C1003.1 C1004.2 C1005.2 C1006.1 C1007.1 C1008.1 C1009.2 C1015.2 C1016.2 C1017.2 C1018.2 C1019.2 C1020.2 C1021.2 C1022.2 C1023.2 C1024.2 C1025.2 C1026.2 C1027.2 C1028.2 C1029.2 C1030.2 C1031.2 C1032.2 C1033.2 C1034.2 C1035.2 C1041.1 C1042.1 C1043.1 C1044.1 C1045.1 C1046.1 C1047.1 C1050.2 C1051.2 C1052.2 C1053.2 C1054.2 C1055.2 C1056.2 C1057.2 C1058.1 C1059.2 C1077.2 C1078.2 C1081.2 C1082.2 C1083.2 C1084.2 C1085.2 C1086.2 C1087.2 C1088.2 C1092.2 C1094.2 C1095.2 C1096.2 C1097.2 C1098.2 CON5.4(GND) CON5.7(GND) CON5.13(GND) CON5.16(GND) CON9.5(GND) CON11.3(GND[0]) CON11.5(GND[1]) CON11.7(GND[2]) CON11.15(GND[3]) CON11.17(GND[4]) CON11.18(GND[5]) CON11.19(GND[6]) CON11.24(GND[7]) D10.3(GND) D10.8(GND) D11.3(GND) D11.8(GND) D13.3(GND) D13.8(GND) J38.4 J38.5 J38.8 J39.2 J59.2 J59.3 J63.2 J63.3 J5006.2 J5010.MINUS J5011.7 J5011.8 J5012.2 J5018.2 J5019.2 J5019.3 J5020.2 LED19.C(CATHODE) P12.5(GND) Q2.2(S) R3.2 R115.1 R116.1 R121.2 R199.1 R222.2 R476.2 R478.2 R480.2 R481.1 R484.1 R487.1 R488.1 R491.1 R493.1 R495.1 R504.1 R507.1 R511.2 R538.2 R548.1 R549.1 R563.2 RN14.5 RN14.6 RN14.7 RN14.8 RN16.5 RN16.6 RN16.7 RN16.8 U2.2(GND/PAD) U5.4(GND) U5.7(GND) U5.13(GND) U5.16(GND) U7.4(VSS) U9.2(GND) U12.3(GND) U12.13(GND) U12.17(GND) U14.1 U15.12(GND) U18.2(GND) U20.1(GND) U26.33(VSS) U39.2(GND) U40.5(GND) U40.9(EPAD) U49.7(GND) U50.2(GND) U50.6(A0) U2027.3 U2027.9 U2027.15 U2027.21 U2027.27 U2027.33 U2027.39 U2027.45 U2027.51 U2027.57 U2027.71 U2027.73 U2027.75 U2029.5(GND) U2029.7(EPAD) U3006.3(GND) U10005.5(GND) U10005.7(EPAD) U10006.2(GND) U10007.2(GND) U10009.6(GND) U10010.6(GND) U10011.AB1(GND) U10011.AB10(GND) U10011.AB11(GND) U10011.AB14(GND) U10011.AB17(GND) U10011.AB20(GND) U10011.AT1(GND) U10011.AT10(GND) U10011.AT11(GND) U10011.AT14(GND) U10011.AT17(GND) U10011.AT20(GND) U10011.BB1(GND) U10011.BB10(GND) U10011.BB11(GND) U10011.BB14(GND) U10011.BB17(GND) U10011.BB20(GND) U10011.BT1(GND) U10011.BT10(GND) U10011.BT11(GND) U10011.BT14(GND) U10011.BT17(GND) U10011.BT20(GND) U10012.1 U10013.4(VSS) U10013.24(VSS) U10013.25(GND) U10014.2(GND) U10015.49(GND/ePAD) U10016.1(E0) U10016.2(E1) U10016.3(E2) U10016.4(GND) U10016.7(~{WC}) U10018.2(GND) U10019.2(GND) Y5.2 Y5.4 ; also on sheet 1 2
GNDC: CON9.SH1 CON9.SH2 P12.SH1 P12.SH2 U5.SH1 U5.SH2 U5.SH3 U5.SH4 U10011.SH ; also on sheet 2
V3P3A_FLT: C26.1 FB2.2 U26.5(VDDA)
VBAT_CONNECTED: U26.26(PB3)
VCC_RTC: D1.3(CATHODE) ; also on sheet 1
10G_INT0: U10011.AT6(MODE_ABS) ; also on sheet 1
10G_INT1: U10011.AB6(MODE_ABS) ; also on sheet 1
10G_INT2: U10011.BT6(MODE_ABS) ; also on sheet 1
10G_INT3: U10011.BB6(MODE_ABS) ; also on sheet 1
10G_SFP_SCL0: U10011.AT5(SCL) ; also on sheet 1
10G_SFP_SCL1: U10011.AB5(SCL) ; also on sheet 1
10G_SFP_SCL2: U10011.BT5(SCL) ; also on sheet 1
10G_SFP_SCL3: U10011.BB5(SCL) ; also on sheet 1
10G_SFP_SDA0: U10011.AT4(SDA) ; also on sheet 1
10G_SFP_SDA1: U10011.AB4(SDA) ; also on sheet 1
10G_SFP_SDA2: U10011.BT4(SDA) ; also on sheet 1
10G_SFP_SDA3: U10011.BB4(SDA) ; also on sheet 1
AB_RS0: R488.2 R489.1 U10011.AB7(RS0)
AB_RS1: R490.1 R491.2 U10011.AB9(RS1)
AB_TX_DIS: RN14.3 U10011.AB3(TX_DISABLE)
AB_VCCR: C1015.1 C1019.1 FB17.2 U10011.AB15(VCCR)
AB_VCCT: C1016.1 C1020.1 FB16.2 U10011.AB16(VCCT)
AT_RS0: R492.1 R493.2
AT_RS1: R494.1 R495.2 U10011.AT9(RS1)
AT_TX_DIS: RN14.1 U10011.AT3(TX_DISABLE)
AT_VCCR: C393.1 C394.1 FB14.2 U10011.AT15(VCCR)
AT_VCCT: C396.1 C397.1 FB15.2 U10011.AT16(VCCT)
ATX_PS_ONn: CON11.16(PS-ON) J39.1 Q2.3(D)
ATX_PWR_OK: CON11.8(PG) R507.2 U3006.1(INB) U3006.2(INA)
BB_RS0: R113.1 R115.2 U10011.BB7(RS0)
BB_RS1: R114.1 R116.2 U10011.BB9(RS1)
BB_TX_DIS: RN14.4 U10011.BB3(TX_DISABLE)
BB_VCCR: C1029.1 C1033.1 FB21.2 U10011.BB15(VCCR)
BB_VCCT: C1030.1 C1034.1 FB20.2 U10011.BB16(VCCT)
BIOS_DIS0#: J5018.1 U26.25(PA15) ; also on sheet 1
BT_RS0: R484.2 R485.1 U10011.BT7(RS0)
BT_RS1: R486.1 R487.2 U10011.BT9(RS1)
BT_TX_DIS: RN14.2 U10011.BT3(TX_DISABLE)
BT_VCCR: C1022.1 C1026.1 FB19.2 U10011.BT15(VCCR)
BT_VCCT: C1023.1 C1027.1 FB18.2 U10011.BT16(VCCT)
BTN_CSRD: C998.1 C999.1 U15.5(CSRD)
BTN_HOLD: D3.1(ANODE1) D3.2(ANODE2) R475.1 R476.1 U15.4(PSHOLD)
BTN_VREF: C997.2 U15.3(VREF)
CB_RESET#: U2027.50 ; also on sheet 1 2
CLK_122p88n: U10015.28(nQ10) ; also on sheet 2
CLK_122p88p: U10015.27(Q10) ; also on sheet 2
CLK_161_BYP_N: U10015.33(nQ9) ; also on sheet 1
CLK_161_BYP_P: U10015.34(Q9) ; also on sheet 1
CLK_SLOT1_N: U2027.53 U10013.13(DIFF0#)
CLK_SLOT1_P: U2027.55 U10013.14(DIFF0)
CLK_SLOT2_N: U10013.15(DIFF1#) ; also on sheet 2
CLK_SLOT2_P: U10013.16(DIFF1) ; also on sheet 2
CLKREQ#: U2027.52
COM_PWRBTN#: U15.8(~{PB}out) ; also on sheet 1
EN: Q2.1(G) U15.9(EN)
EN_OCXO: R536.1 U49.2(EN)
HDD_LED+: J38.1 R502.2
I2C_PTP_SCL_R: R224.1 R227.2 U10015.8(SCL_M) U10016.6(SCL)
I2C_PTP_SDA_R: R225.1 R228.2 U10015.7(SDA_M) U10016.5(SDA)
I2C_SCL: R500.2 ; also on sheet 1 2
I2C_SDA: R501.2 ; also on sheet 1 2
IDT_RESET: R565.1 TP45.1(TP) U39.1(RESET#) U10015.17(nMR)
INT#: U15.11(~{INT})
MASTER_RESET#: R503.1 U26.27(PB4)
MCU_ADC_IN8: R37.1 R504.2 U26.14(PB0)
MCU_ADC_IN9: U26.15(PB1)
MCU_I2C1_SCK: R200.2 R499.2 RN15.2 U26.29(PB6)
MCU_I2C1_SDA: R78.2 R498.2 RN15.1 U26.30(PB7)
MCU_RESET: R198.1 U26.4(NRST)
MCU_SPI1_CS: U26.10(PA4) U10009.2(NO1)
MCU_SPI1_MISO: U26.12(PA6) U10010.2(NO1)
MCU_SPI1_MOSI: U26.13(PA7) U10010.10(NO2)
MCU_SPI1_SCK: U26.11(PA5) U10009.10(NO2)
MCU_SPI1_SWITCH: R481.2 U26.16(PB2) U10009.4(SEL1) U10009.8(SEL2) U10010.4(SEL1) U10010.8(SEL2)
MCU_USART1_RX: J5006.1 U12.2(RXD) U26.20(PA10) ; also on sheet 1
MCU_USART1_TX: R497.1 U26.19(PA9)
MCU_USART2_RX: TP124.1 U26.9(PA3)
MCU_USART2_TX: TP125.1 U26.8(PA2)
NVME_LED#: J38.3 U2027.10 U10014.1(IO1)
OCXO_CLK_OUT: U49.4(OUT) U10015.1(XO_DPLL) U10019.3(RF_OUT)
OCXO_VCTRL: U49.1(V_CTRL) U50.1(VOUT)
PCIE_CKREF_N: U10013.23(DIFF_IN#) ; also on sheet 1
PCIE_CKREF_P: U10013.22(DIFF_IN) ; also on sheet 1
PCIE_RXN0: U2027.41 ; also on sheet 1
PCIE_RXN1: U2027.29 ; also on sheet 1
PCIE_RXN2: U2027.17 ; also on sheet 1
PCIE_RXN3: U2027.5 ; also on sheet 1
PCIE_RXN16: U10011.AT12(RX-) ; also on sheet 1
PCIE_RXN17: U10011.AB12(RX-) ; also on sheet 1
PCIE_RXN18: U10011.BT12(RX-) ; also on sheet 1
PCIE_RXN19: U10011.BB12(RX-) ; also on sheet 1
PCIE_RXP0: U2027.43 ; also on sheet 1
PCIE_RXP1: U2027.31 ; also on sheet 1
PCIE_RXP2: U2027.19 ; also on sheet 1
PCIE_RXP3: U2027.7 ; also on sheet 1
PCIE_RXP16: U10011.AT13(RX+) ; also on sheet 1
PCIE_RXP17: U10011.AB13(RX+) ; also on sheet 1
PCIE_RXP18: U10011.BT13(RX+) ; also on sheet 1
PCIE_RXP19: U10011.BB13(RX+) ; also on sheet 1
PCIE_TXN0: U2027.47 ; also on sheet 1
PCIE_TXN1: U2027.35 ; also on sheet 1
PCIE_TXN2: U2027.23 ; also on sheet 1
PCIE_TXN3: U2027.11 ; also on sheet 1
PCIE_TXN16: U10011.AT19(TX-) ; also on sheet 1
PCIE_TXN17: U10011.AB19(TX-) ; also on sheet 1
PCIE_TXN18: U10011.BT19(TX-) ; also on sheet 1
PCIE_TXN19: U10011.BB19(TX-) ; also on sheet 1
PCIE_TXP0: U2027.49 ; also on sheet 1
PCIE_TXP1: U2027.37 ; also on sheet 1
PCIE_TXP2: U2027.25 ; also on sheet 1
PCIE_TXP3: U2027.13 ; also on sheet 1
PCIE_TXP16: U10011.AT18(TX+) ; also on sheet 1
PCIE_TXP17: U10011.AB18(TX+) ; also on sheet 1
PCIE_TXP18: U10011.BT18(TX+) ; also on sheet 1
PCIE_TXP19: U10011.BB18(TX+) ; also on sheet 1
PEWAKE#: U2027.54
PHY0_RECOVERED_CLK: J5019.1 U10015.4(CLK1)
PHY1_RECOVERED_CLK: U10015.5(nCLK1) ; also on sheet 1
PLA#: U2027.30
PLN#: U2027.8
PPS: U10015.2(CLK0) ; also on sheet 1
PPS_IN_UFL: R539.1 ; also on sheet 2
PTP_CP0_PCLK_OUT: TP139.1(TP) U10015.3(nCLK0)
PTP_CREG_XTAL: C400.2 U10015.43(CREG_XTAL)
PTP_FLTR: C410.2 U10015.14(FILTER)
PTP_GPIO8: R223.1 U10015.25(GPIO8)
PTP_GPIO9: R537.1 R538.1 TP36.1(TP) U10015.24(GPIO9)
PTP_JTAG_TCK: RN16.1 TP29.1(TP) U10015.42(GPIO0)
PTP_JTAG_TDI: RN16.4 TP32.1(TP) U10015.29(GPIO2)
PTP_JTAG_TDO: TP31.1(TP) U10015.19(GPIO3)
PTP_JTAG_TMS: RN16.3 TP30.1(TP) U10015.32(GPIO1)
PTP_JTAG_TRST_N: R222.1 TP33.1(TP) U10015.37(GPIO4)
PTP_LOS: RN16.2 TP34.1(TP) U10015.36(GPIO5)
PTP_OSCI: C405.2 U10015.45(OSCI) Y5.3
PTP_OSCO: C406.1 U10015.44(OSCO) Y5.1
PTP_SE_OUTPUT_N: J63.1 U10015.41(nQ8)
PTP_SE_OUTPUT_P: J59.1 R539.2 U10015.40(Q8)
PTP_TEST_N: R226.1 U10015.18(nTEST)
PWR_BTN: D15.3(CATHODE) U26.28(PB5)
PWR_OK: U3006.4(OUT) ; also on sheet 1
PWRBTN_CNTRLR#: C1.1 C2.1 D8.1(ANODE1) D8.2(ANODE2) D14.1(ANODE1) D14.2(ANODE2) D15.1(ANODE1) D15.2(ANODE2) U15.2(~{SR}) U15.6(~{PB}) U10012.2
PWRBTN_PANEL#: D14.3(CATHODE) J38.6 U10014.4(IO3)
RST#: U15.10(~{RST})
SEC_SPI_3v0: C58.1 D12.3(CATHODE) R22.2 R23.2 R508.2 U7.8(VCC) U10009.1(VCC) U10010.1(VCC)
SEC_SPI_CLK: C103.2 U7.6(C) U10009.9(COM2)
SEC_SPI_CS#: R508.1 U7.1(~{S}) U10009.3(COM1)
SEC_SPI_MISO: U7.2(Q) U10010.3(COM1)
SEC_SPI_MOSI: U7.5(D) U10010.9(COM2)
SER0_RX: J5006.3 R496.2 R497.2 ; also on sheet 1
SER1_RX: J5012.3 ; also on sheet 1
SER1_TX: J5012.1 ; also on sheet 1
SMB_CLK: R227.1 R498.1 R546.2 U50.5(SCL) ; also on sheet 1 2
SMB_SDA: R228.1 R499.1 R547.2 U50.4(SDA) ; also on sheet 1 2
SPI_CLK: U10009.7(NC2) ; also on sheet 1
SPI_CS#: U10009.5(NC1) ; also on sheet 1
SPI_MISO: U10010.5(NC1) ; also on sheet 1
SPI_MOSI: U10010.7(NC2) ; also on sheet 1
SPI_NOR_HOLD_B: R22.1 U7.7(~{HOLD})
SPI_NOR_WP: R23.1 U7.3(~{W}/VPP)
SPI_POWER: D12.1(ANODE1) ; also on sheet 1
SUS_S5#: D3.3(CATHODE) ; also on sheet 1
SYS_RESET#: C94.1 J38.7 R503.2 R564.1 U14.2 U10014.3(IO2) ; also on sheet 1
USB0_DN: U5.2(D1-) U10007.1(IO1) ; also on sheet 1
USB0_DP: U5.3(D1+) U10007.3(IO2) ; also on sheet 1
USB1_DN: CON5.8(P1_D-) U18.3(IO2) ; also on sheet 1
USB1_DP: CON5.9(P1_D+) U18.1(IO1) ; also on sheet 1
USB2_DN: U5.11(D2-) U10007.6(IO4) ; also on sheet 1
USB2_DP: U5.12(D2+) U10007.4(IO3) ; also on sheet 1
USB_DM: C994.1 P12.2(D-) R473.1
USB_DP: C995.1 P12.3(D+) R474.1
USB_FT_DM: R473.2 U26.21(PA11)
USB_FT_DP: R474.2 U26.22(PA12)
USB_N2: CON5.12(P2_D-) U18.4(IO3) ; also on sheet 2
USB_N3: J5011.3 U10006.3(IO2) ; also on sheet 2
USB_N4: J5011.4 U10006.4(IO3) ; also on sheet 2
USB_P2: CON5.11(P2_D+) U18.6(IO4) ; also on sheet 2
USB_P3: J5011.5 U10006.1(IO1) ; also on sheet 2
USB_P4: J5011.6 U10006.6(IO4) ; also on sheet 2
USB_SSRX_N0: D10.2(I/O2) D10.9(NC) U5.5(SSRX1-) ; also on sheet 1
USB_SSRX_N1: CON5.2(P1_RX-) D11.1(I/O1) D11.10(NC) ; also on sheet 1
USB_SSRX_N2: D10.5(I/O4) D10.6(NC) U5.14(SSRX2-) ; also on sheet 1
USB_SSRX_P0: D10.1(I/O1) D10.10(NC) U5.6(SSRX1+) ; also on sheet 1
USB_SSRX_P1: CON5.3(P1_RX+) D11.2(I/O2) D11.9(NC) ; also on sheet 1
USB_SSRX_P2: D10.4(I/O3) D10.7(NC) U5.15(SSRX2+) ; also on sheet 1
USB_SSTX_N0: D13.1(I/O1) D13.10(NC) U5.8(SSTX1-) ; also on sheet 1
USB_SSTX_N1: CON5.5(P1_TX-) D11.4(I/O3) D11.7(NC) ; also on sheet 1
USB_SSTX_N2: D13.4(I/O3) D13.7(NC) U5.17(SSTX2-) ; also on sheet 1
USB_SSTX_P0: D13.2(I/O2) D13.9(NC) U5.9(SSTX1+) ; also on sheet 1
USB_SSTX_P1: CON5.6(P1_TX+) D11.5(I/O4) D11.6(NC) ; also on sheet 1
USB_SSTX_P2: D13.5(I/O4) D13.6(NC) U5.18(SSTX2+) ; also on sheet 1
V_5: C1001.2 C1006.2 C1042.2 C1043.2 C1044.2 C1045.2 CON11.4(+5V[0]) CON11.6(+5V[1]) CON11.21(+5V[2]) CON11.22(+5V[3]) CON11.23(+5V[4]) U2029.4(EN) U2029.6(IN) U10005.4(EN) U10005.6(IN)
V_5_SB: C3.1 C1046.2 C1047.2 CON11.9(+5VSB) U2.1(VIN) ; also on sheet 1
V_5V0_4P_USB_2_0: C1005.1 C1007.2 C1008.2 C1009.1 J5011.1 J5011.2 U5.1(VBUS1) U5.10(VBUS2) U10005.1(OUT) U10006.5(VBUS) U10007.5(VBUS)
V_5V0_USB3_HDR_VBUS: C1000.1 C1002.2 C1003.2 C1004.1 CON5.1(VBUS) CON5.19(VBUS) J38.2 J38.9 U18.5(VBUS) U2029.1(OUT) U10014.5(VBUS)
V_MGT_3p3: C236.1 C429.1 C989.1 D12.2(ANODE2) FB2.1 J5017.1 R78.1 R197.2 R198.2 R200.1 RN15.5 RN15.6 RN15.7 RN15.8 U9.4(VOUT) U26.1(VDD) U26.17(VDDIO2)
V_MGT_5p0: C988.2 C993.1 L16.2 U9.1(EN) U9.3(VIN)
N17088991: C93.2 C972.1 U12.1(VCCIO) U12.8(3V3OUT) U12.9(RESET#)
N17089017: C87.1 C88.2 FB1.1 U12.10(VCC)
N17089025: CON9.1(VBUS) FB1.2
N17089039: CON9.3(D+) U12.6(USBDP)
N17089060: CON9.2(D-) U12.7(USBDM)
N18534349: LED19.A(ANODE) R467.2
N18690247: C4.1 C996.1 D8.3(CATHODE) R3.1 U2.3(VOUT) U15.1(VCC)
N18691020: D1.2(ANODE2) R41.2
N18691058: J5010.PLUS R41.1
N18691864: C237.1 U9.6(BYP)
N18691932: C992.1 L16.1 P12.1(VBUS)
N18693405: J5017.2 R197.1 R199.2 U26.31(BOOT0-PF11)
N18710663: R478.1 U2029.2(ILIM)
N18769152: R496.1 U12.15(TXD)
N18795708: C1050.1 C1053.1 C1054.1 C1055.1 C1056.1 C1057.1 FB22.2 U10013.1(VDD) U10013.3(VDD) U10013.5(OE_DIFF0) U10013.6(VDD) U10013.12(VDD) U10013.17(VDD) U10013.18(OE_DIFF1) U10013.21(VDD)
N18799422: R500.1 U10013.19(SCK)
N18799425: R501.1 U10013.20(SDA)
N18863454: R480.1 U10005.2(ILIM)
N18897049: R511.1 U2027.38
N18979518: C1078.1 L17.2 U50.3(VDD)
N18979820: TP130.1(TP) U10015.21(Q11)
N18979834: TP131.1(TP) U10015.20(nQ11)
N18999566: J5020.1 R546.1 U10015.12(SCLK_AUX)
N18999575: J5020.3 R547.1 U10015.11(SDIO_AUX)
N18999599: R548.2 U10015.9(CS_A0_AUX)
N18999617: R549.2 U10015.10(SDI_A1_AUX)
N19032758: TP137.1(TP) U39.3(MR#)
N19032785: R121.1 R132.2 U39.5(SENSE)
N19032793: C206.1 U39.4(CT)
N19034097: R564.2 TP136.1(TP) U10018.1(RESET#)
N19034133: TP138.1(TP) U10018.3(MR#)
N19034158: R562.2 R563.1 U10018.5(SENSE)
N19034166: C1095.1 U10018.4(CT)

Not connected (* = marked no-connect by the designer): CON5 10(ID) 14(P2_TX+) 15(P2_TX-) 17(P2_RX+) 18(P2_RX-); CON9 4(ID)*; CON11 14(-12V) 20(-5V); J34 1; J5007 1; J5008 1; J5011 9*; P12 4(ID)*; RN15 3 4; U9 5(NC)*; U12 4(CTS#)* 5(CBUS2)* 11(CBUS1)* 12(CBUS0)* 14(CBUS3)* 16(RTS#)*; U15 7(~{VCC}lo)*; U26 2(PF0-OSC_IN) 3(PF1-OSC_OUT) 6(PA0) 7(PA1) 18(PA8) 23(PA13) 24(PA14) 32(PB8); U40 3(NC)*; U49 5(NC-1) 6(NC-2); U2027 1 6* 20* 22* 24* 26* 28* 32* 34* 36* 40* 42* 44* 46* 48* 56* 58* 59* 60* 61* 62* 63* 64* 65* 66* 67 68 69; U2029 3(FLAG#); U10005 3(FLAG#); U10011 AB2(TX_FAULT) AB8(LOS) AT2(TX_FAULT)* AT7(RS0) AT8(LOS)* BB2(TX_FAULT) BB8(LOS) BT2(TX_FAULT) BT8(LOS); U10014 6(IO4)*; U10019 1(NC)

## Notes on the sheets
sheet 3
- USB 2.0/3.0 host and header connector
- M.2 M key (NVME)
- Reset button and header
- Bring LED to the front?
- Notice that the dual USB 3.0 header that is intended to be used
  with standard PC chassis USB 3.0 front panel will support a single USB 3.0
  and the second USB will be only USB 2.0.
- Reset header can be brought to front panel
- RESET button
- SUSCLK
- PEDET
- VBUS bleeds into PWRBTN_PANEL# as a pull-upl
  Do not assemble this part.
- NVME 2280
- NVME 2242
- NVME 22110
- Management interface.
  I2C goes to a fixed local EEPROM that has board signature.
  SPI goes to local application processor boot flash
  UART goes to local application processor UART console interface
- Micro BMC
- Workaround for LX2160A rev 1.3 bug not having pull-up on CS
- When jumper inserted; MCU DFU boots
- PA8..PA15 are supplied by VDDIO2
- Onboard micro USB to serial console
sheet 4
- Power-on push button controller
- 2x2 SFP+ connector
- 43mA @ 24V
- 18.5mA @ 12V
- 3.3V@0.33mA
- Vih = 1.05V
- OPEN DRAIN
- OPEN DRAIN
- INT. 100K PU
- RESET button
- ATX PSU connector
- Timing constant = 10s/uF
- Only 12v part is used. Notice the pin 16 to GND short
  that enables the PSU.
- Notes -
  1. The push-butoon controller is configured in a way that powers-on when ATX power is available.
  2. COM express type 7 can shutdnwo the ATX PSU via SUS_S5# signal.
  3. STM32 MCU (micro BMC) can shutdown the motherboard using PWRBTN_CNTRLR# signal.
  3. PC workstation front panel can shutdown the motherboard via PWRBTN_PANEL# signal
  4. COM express type #7 can get indication of power-button being pressed by COM_PWRBTN# (and thus start a shutdown process).
- PCIe clock buffer. Input from COM express type 7 and
  output is connected to the NVME M.2 connector and
  PCIe x8 open-slot connector
- By default DNP.
sheet 5
- 1588v2 & SYNCE
- 122.88 MHz
- During warm up 4W
  SS @ 25degC 1.5W
- shared pad
- Max 300mA
- Max 60mA
- 10MHz
- EEPROM Address
  0x4C
- GPS PPS
- Max 24mA
- SyncE
- 161.1328125 MHz
- 122.88 MHz
- Max 133mA
- 26mA
- I2C Address
  0b1010011
  0x5B
- 5mA
- I2C Address
  0b1010000
  0x50
- 5mA
- 5mA
- 5mA
- 5mA
- 5mA
- 5mA
- 5mA
- 2.7 seconds delay. will give enough time for the IDT clock gen to stabilize the clocks.
  IDT requirement is 1.5 seconds after it's RESET deassertion
- Triggres SENSE on 0.6v
- Triggres SENSE on 0.6v
- 10nF delays the RESET# with 50mS
- 470nFnF delays the RESET# with ~2.7 seconds
